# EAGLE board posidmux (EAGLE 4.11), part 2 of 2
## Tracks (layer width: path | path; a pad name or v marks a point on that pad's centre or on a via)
+3V3  (via drill 0.61)
  Top 0.381: D5.C D4.C D6.C D3.C D1.C D8.C D2.C D7.C D12.C D13.C D11.C D14.C D10.C D15.C D9.C D16.C 68.58,106.68 v69.85,107.95
  Bottom 0.381: v69.85,107.95 69.85,108.58 86.36,125.09 XESS.54
AC00  (via drill 0.61)
  Top 0.381: v32.38,87.63 29.21,87.63 27.94,88.9 E27.2 | v31.75,99.06 31.11,98.42 v10.16,98.42 | R37.1 SV3.D
  Bottom 0.381: v32.38,87.63 32.38,98.42 v31.75,99.06 | v10.16,98.42 5.71,93.98 5.71,38.1 16.51,27.3 16.51,12.7 19.05,10.16 63.5,10.16 R37.1 | SV2.6 55.88,43.81 58.42,41.27 58.42,33.66 57.78,33.02 56.52,33.02 55.88,32.38 55.88,24.77 57.15,23.5 57.15,19.68 57.78,19.05 62.87,19.05 62.87,20.32 SV3.D
AC01  (via drill 0.61)
  Top 0.381: v20.32,88.9 19.05,90.17 v1.27,90.17 | v1.27,34.92 17.14,19.05 v52.07,19.05 56.52,19.05 57.78,20.32 SV3.J R39.1
  Bottom 0.381: v20.32,88.9 20.32,86.36 E27.4 | v1.27,34.92 v1.27,90.17 | v52.07,19.05 52.07,23.5 53.34,24.77 SV2.8
AC02  (via drill 0.61)
  Top 0.381: v26.67,76.83 26.04,76.83 24.13,78.74 E27.6 | v32.38,57.15 36.83,57.15 45.72,48.26 46.35,48.26 | 46.35,48.26 46.99,47.62 46.99,45.09 48.26,45.09 SV2.12 | v64.77,45.09 61.59,48.26 46.35,48.26
  Bottom 0.381: SV3.N R41.1 53.98,12.7 55.24,11.43 62.23,11.43 62.23,17.14 64.77,19.68 v64.77,45.09 | v26.67,76.83 28.57,74.93 28.57,73.03 29.21,72.39 32.38,72.39 v32.38,57.15
AC03  (via drill 0.61)
  Top 0.381: v32.38,74.93 29.21,74.93 27.94,73.66 E27.8 | v33.66,55.88 41.91,47.62 41.91,45.09 43.18,45.09 SV2.16 | v43.18,30.48 46.99,30.48 46.99,22.23 48.26,20.95 SV3.T
  Bottom 0.381: R43.1 SV3.T | v32.38,74.93 33.66,73.66 v33.66,55.88 | v43.18,30.48 SV2.16
AC04  (via drill 0.61)
  Top 0.381: v34.29,45.72 36.2,45.72 37.47,44.45 SV2.20 | v33.02,30.48 41.91,30.48 41.91,22.23 43.18,20.95 SV3.X
  Bottom 0.381: R45.1 SV3.X | E27.11 31.11,67.94 31.11,50.8 34.29,47.62 v34.29,45.72 34.29,43.81 33.02,42.55 v33.02,30.48
AC05  (via drill 0.61)
  Top 0.381: v27.94,71.75 28.57,71.75 E27.13 | v27.94,50.8 27.94,48.26 28.57,48.26 29.21,47.62 29.21,45.72 31.11,45.72 32.38,44.45 SV2.24 33.02,43.81 v38.1,38.73
  Bottom 0.381: R47.1 SV3.BB 38.1,20.95 36.83,22.23 36.83,29.84 38.1,31.11 v38.1,38.73 | v27.94,50.8 v27.94,71.75
AC06  (via drill 0.61)
  Top 0.381: v20.95,50.8 24.13,47.62 24.13,45.72 26.04,45.72 27.3,44.45 SV2.28
  Bottom 0.381: R49.1 SV3.FF 33.02,20.95 31.75,22.23 31.75,29.84 30.48,31.11 30.48,41.27 27.94,43.81 SV2.28 | v20.95,50.8 20.95,80.01 24.13,80.01 24.77,80.64 24.77,82.55 31.75,82.55 32.38,81.92 32.38,80.64 E27.15
AC07
  Top 0.381: 4.45,51.44 4.45,49.53 13.34,49.53 19.68,43.18 23.5,43.18 24.77,44.45 SV2.30 | 4.45,51.44 4.45,80.01 6.99,82.55 11.43,82.55 12.7,81.28 14.61,81.28 15.88,80.01 25.4,80.01 29.21,83.82 E27.17 | 4.45,51.44 1.27,51.44 1.27,49.53 21.59,29.21 29.21,29.21 29.21,22.23 27.94,20.95 SV3.LL
  Bottom 0.381: R51.1 SV3.LL
AC08  (via drill 0.61)
  Top 0.381: v20.95,82.55 25.4,82.55 27.94,85.09 31.75,85.09 E25.2
  Bottom 0.381: SV3.RR R53.1 22.23,12.7 20.95,11.43 19.05,11.43 19.05,40.01 22.86,43.81 SV2.32 22.86,45.09 21.59,46.35 21.59,47.62 19.68,49.53 19.68,81.28 v20.95,82.55
AC09  (via drill 0.61)
  Top 0.381: v57.78,80.01 40.64,80.01 36.83,83.82 E25.4 | R38.1 SV3.F
  Bottom 0.381: v57.78,80.01 58.42,79.38 58.42,51.44 63.5,46.35 63.5,26.04 | 63.5,26.04 63.5,24.77 62.23,23.5 62.23,22.23 60.96,20.95 SV3.F | 63.5,26.04 57.78,31.75 SV1.6
AC10  (via drill 0.61)
  Top 0.381: v49.53,59.69 v38.73,59.69
  Bottom 0.381: R40.1 SV3.L 55.88,20.95 54.61,22.23 SV1.8 54.61,32.38 55.88,33.66 55.88,34.92 54.61,36.2 54.61,47.62 52.7,49.53 52.7,56.52 v49.53,59.69 | v38.73,59.69 38.73,76.83 36.83,78.74 E25.6
AC11  (via drill 0.61)
  Top 0.381: v40.01,55.88 46.35,49.53 v50.16,49.53 | v40.01,69.22 E25.8
  Bottom 0.381: R42.1 SV3.R 50.8,20.95 49.53,22.23 SV1.12 49.53,32.38 50.8,33.66 50.8,34.92 52.07,36.2 52.07,47.62 v50.16,49.53 | v40.01,55.88 v40.01,69.22
BAC  (via drill 0.61)
  Top 0.381: E12.11 147.96,67.94 147.96,64.77 158.75,64.77 161.29,67.31 163.83,67.31 166.37,69.85 190.5,69.85 191.77,68.58 E1.11 | v146.05,144.78 90.17,144.78 90.17,142.88 85.72,138.43 6.99,138.43 6.99,125.09 E29.6
  Bottom 0.381: v146.05,144.78 146.05,106.05 140.97,100.97 140.97,92.71 142.24,91.44 142.24,73.66 E12.11
BAC00  (via drill 0.61)
  Top 0.381: v159.38,86.36 E11.3
  Bottom 0.381: SV9.D 182.88,15.88 180.34,13.34 R1.1 179.71,12.7 178.44,11.43 171.45,11.43 171.45,17.14 173.99,19.68 173.99,29.84 172.72,31.11 172.72,43.18 | v159.38,86.36 159.38,61.59 161.29,59.69 167.64,59.69 167.64,51.44 171.45,47.62 171.45,43.81 172.09,43.18 172.72,43.18 | 172.72,43.18 174.62,43.18 174.62,44.45 SV8.6
BAC01  (via drill 0.61)
  Top 0.381: v181.61,21.59 179.71,21.59 178.44,20.32 SV9.J | v180.34,36.2 172.72,43.81 SV8.8
  Bottom 0.381: R3.1 175.26,13.34 177.8,15.88 SV9.J | E11.5 168.28,78.11 168.28,60.33 168.91,59.69 173.99,59.69 173.99,46.35 172.72,45.09 SV8.8 | v181.61,21.59 181.61,29.84 180.34,31.11 v180.34,36.2
BAC02  (via drill 0.61)
  Top 0.381: v153.67,43.18 165.74,43.18 167,44.45 SV8.12 | v156.21,21.59 170.81,21.59 172.09,20.32 SV9.N
  Bottom 0.381: R5.1 170.18,17.14 172.72,19.68 SV9.N | E9.3 153.03,59.05 153.03,48.26 153.67,47.62 v153.67,43.18 154.94,41.91 154.94,31.11 156.21,29.84 v156.21,21.59
BAC03
  Bottom 0.381: R7.1 165.1,13.34 167.64,15.88 SV9.T 167.64,20.95 166.37,22.23 166.37,29.84 165.1,31.11 165.1,41.27 162.56,43.81 SV8.16 162.56,45.09 163.83,46.35 163.83,57.15 E9.5
BAC04  (via drill 0.61)
  Top 0.381: v151.76,52.07 156.21,47.62 156.21,45.09 157.48,45.09 SV8.20
  Bottom 0.381: R9.1 160.02,13.34 162.56,15.88 SV9.X 162.56,20.95 161.29,22.23 161.29,29.84 160.02,31.11 160.02,41.27 157.48,43.81 SV8.20 | v151.76,52.07 151.76,70.48 E10.3
BAC05  (via drill 0.61)
  Top 0.381: v150.5,67.31 157.48,67.31 161.29,71.12 E10.5
  Bottom 0.381: SV9.BB 157.48,15.88 154.94,13.34 R11.1 154.31,12.7 153.03,11.43 148.59,11.43 148.59,17.14 151.13,19.68 151.13,23.5 149.86,24.77 149.86,41.27 152.4,43.81 SV8.24 152.4,45.09 151.13,46.35 151.13,47.62 150.5,48.26 v150.5,67.31
BAC06  (via drill 0.61)
  Top 0.381: E7.5 173.99,71.12 171.45,73.66 E7.3 168.91,73.66 167.64,72.39 v151.76,72.39 | v147.32,29.84 153.67,23.5 153.67,20.95 152.4,20.95 SV9.FF
  Bottom 0.381: R13.1 149.86,13.34 152.4,15.88 SV9.FF | v147.32,29.84 SV8.28 147.32,45.09 148.59,46.35 148.59,47.62 149.22,48.26 149.22,69.85 v151.76,72.39
BAC07
  Bottom 0.381: R15.1 144.78,13.34 146.05,14.61 146.05,18.41 147.32,19.68 SV9.LL 147.32,21.59 144.15,21.59 143.51,22.23 143.51,23.5 144.78,24.77 SV8.30
BAC08  (via drill 0.61)
  Top 0.381: v147.96,59.69 167.64,59.69 168.91,60.96 E6.3
  Bottom 0.381: R17.1 139.7,13.34 142.24,15.88 SV9.RR 142.24,20.95 140.97,22.23 140.97,29.84 142.24,31.11 SV8.32 142.24,45.09 143.51,46.35 143.51,55.24 v147.96,59.69
BAC09  (via drill 0.61)
  Top 0.381: v180.97,55.88 180.34,55.88 E6.5
  Bottom 0.381: R2.1 177.8,13.34 180.34,15.88 SV9.F 180.34,20.95 179.07,22.23 179.07,28.57 176.53,31.11 SV7.6 176.53,32.38 177.8,33.66 177.8,34.92 179.07,36.2 179.07,47.62 180.97,49.53 v180.97,55.88
BAC10  (via drill 0.61)
  Top 0.381: v179.71,85.09 172.72,85.09 171.45,86.36 E8.3
  Bottom 0.381: R4.1 172.72,13.34 175.26,15.88 SV9.L 175.26,20.95 176.53,22.23 176.53,28.57 173.99,31.11 SV7.8 173.99,32.38 175.26,33.66 175.26,34.92 176.53,36.2 176.53,52.07 179.71,55.24 179.71,62.87 182.25,65.41 182.25,82.55 v179.71,85.09
BAC11  (via drill 0.61)
  Top 0.381: v174.62,60.96 172.72,59.05 v172.72,58.42 | v172.72,52.07 v168.91,48.26 | v173.99,83.82 E8.5
  Bottom 0.381: R6.1 167.64,13.34 168.91,14.61 168.91,18.41 170.18,19.68 SV9.R 170.18,20.95 168.91,22.23 SV7.12 168.91,32.38 167.64,33.66 167.64,34.92 168.91,36.2 v168.91,48.26 | v173.99,83.82 173.99,61.59 v174.62,60.96 | v172.72,58.42 v172.72,52.07
BACL
  Top 0.381: E28.7 21.59,119.38 20.32,118.11 16.51,118.11 E29.5
BACLR
  Bottom 0.381: R48.1 SV3.DD 35.56,20.95 34.29,22.23 SV1.24 34.29,32.38 35.56,33.66 35.56,34.92 36.83,36.2 36.83,47.62 43.18,53.98 43.18,67.31 41.91,67.31 41.27,67.94 41.27,71.75 E25.13
BINIT  (via drill 0.61)
  Top 0.381: v179.07,97.16 175.9,93.98 v136.53,93.98 | SV7.32 143.51,31.11 135.89,23.5 135.89,21.59 137.79,21.59 139.06,20.32 SV9.TT
  Bottom 0.381: 138.43,14.61 139.7,15.88 SV9.TT | 138.43,14.61 137.16,13.34 R18.1 | v179.07,97.16 179.07,127 182.88,130.81 E4.5 | v136.53,93.98 136.53,25.4 138.43,23.5 138.43,14.61
BIOP1  (via drill 0.61)
  Top 0.381: v195.58,99.06 184.78,109.86 182.25,109.86 E3.3
  Bottom 0.381: 163.83,14.61 165.1,15.88 SV9.V | 163.83,14.61 162.56,13.34 R8.1 | v195.58,99.06 195.58,20.95 185.42,10.79 185.42,5.71 180.97,1.27 163.83,1.27 163.83,14.61 | 163.83,14.61 SV7.16
BIOP2  (via drill 0.61)
  Top 0.381: v190.5,123.19 186.69,123.19 E3.5 | v200.66,33.66 186.06,19.05 161.93,19.05 160.66,20.32 SV9.Z
  Bottom 0.381: 158.75,14.61 160.02,15.88 SV9.Z | 158.75,14.61 157.48,13.34 R10.1 | v190.5,123.19 193.04,123.19 193.04,114.3 200.66,106.68 v200.66,33.66 | 158.75,14.61 SV7.20
BIOP4  (via drill 0.61)
  Top 0.381: v190.5,93.98 185.42,93.98 E2.3 | v189.23,37.47 182.25,30.48 155.57,30.48 154.31,31.75 SV7.24
  Bottom 0.381: R12.1 152.4,13.34 154.94,15.88 SV9.DD 154.94,20.95 153.67,22.23 SV7.24 | v190.5,93.98 190.5,55.24 189.23,53.98 v189.23,37.47
BIRQ
  Bottom 0.381: R46.1 SV3.Z 40.64,20.95 39.37,22.23 SV1.20 39.37,32.38 40.64,33.66 40.64,34.92 41.91,36.2 41.91,41.27 39.37,43.81 39.37,47.62 45.09,53.34 45.09,76.83 E25.15
BMB
  Bottom 0.381: 68.58,10.79 68.58,67.31 69.85,68.58 E23.11 | 68.58,10.79 70.48,8.89 132.08,8.89 E13.11 | 68.58,10.79 68.58,1.27 19.68,1.27 3.81,17.14 3.81,125.73 E29.2
BMB00  (via drill 0.61)
  Top 0.381: SV6.D R19.1 | v61.59,57.15 76.83,41.91 111.12,41.91 112.39,43.18 | 112.39,43.18 113.67,44.45 SV5.6 | v125.09,39.37 121.28,43.18 112.39,43.18
  Bottom 0.381: v61.59,57.15 61.59,72.39 64.77,72.39 67.94,75.56 67.94,80.01 72.39,80.01 73.03,80.64 73.03,81.92 77.47,86.36 E22.3 | v125.09,39.37 123.19,37.47 123.19,22.23 121.92,20.95 SV6.D
BMB01  (via drill 0.61)
  Top 0.381: v104.78,85.09 88.9,85.09 87.63,83.82 E22.5 | v111.76,30.48 118.11,30.48 118.11,22.23 116.84,20.95 SV6.J
  Bottom 0.381: R21.1 SV6.J | v104.78,85.09 106.05,86.36 106.05,88.27 107.95,90.17 113.03,90.17 113.03,46.35 111.76,45.09 SV5.8 v111.76,30.48
BMB02  (via drill 0.61)
  Top 0.381: v74.3,46.99 78.11,43.18 104.78,43.18 106.05,44.45 SV5.12 | v74.3,73.66 E21.3
  Bottom 0.381: R23.1 SV6.N 111.12,20.32 109.86,21.59 107.95,21.59 107.95,29.84 106.68,31.11 SV5.12 | v74.3,46.99 v74.3,73.66
BMB03  (via drill 0.61)
  Top 0.381: v99.06,40.64 v96.52,40.64
  Bottom 0.381: SV6.X R27.1 100.97,12.7 99.69,11.43 95.25,11.43 95.25,29.84 96.52,31.11 96.52,37.47 99.06,40.01 v99.06,40.64 | 88.27,73.03 89.53,74.3 89.53,87 E19.1 | 88.27,73.03 E21.5 | 88.27,73.03 88.27,61.59 92.71,57.15 92.71,43.18 94.61,43.18 95.89,44.45 SV5.20 v96.52,40.64
BMB03L  (via drill 0.61)
  Top 0.381: v118.75,53.34 113.67,48.26 100.97,48.26 100.33,47.62 100.33,45.09 101.6,45.09 SV5.16
  Bottom 0.381: R25.1 SV6.T 106.68,20.95 105.41,22.23 105.41,27.3 101.6,31.11 SV5.16 | v118.75,53.34 118.75,92.71 100.33,92.71 E19.3
BMB04  (via drill 0.61)
  Top 0.381: v97.16,64.77 92.71,64.77 87.63,59.69 81.28,59.69 80.01,60.96 E20.3 | v95.25,45.72 88.27,45.72 87,44.45 SV5.28 | v83.82,30.48 90.17,30.48 90.17,22.23 91.44,20.95 SV6.FF
  Bottom 0.381: R31.1 SV6.FF | E19.6 97.79,82.55 97.79,65.41 v97.16,64.77 97.16,55.88 95.25,53.98 v95.25,45.72 | v83.82,30.48 83.82,40.01 86.36,42.55 SV5.28
BMB04L  (via drill 0.61)
  Top 0.381: v99.06,73.66 95.25,69.85 90.17,69.85 87.63,67.31 85.09,67.31 v82.55,64.77 | v76.83,30.48 59.69,30.48 59.69,22.23 60.33,21.59 64.77,21.59 64.77,19.68 65.41,19.05 94.61,19.05 95.89,20.32 SV6.BB
  Bottom 0.381: SV6.BB R29.1 | v99.06,73.66 99.06,82.55 100.33,83.82 E19.5 | 82.55,50.16 82.55,46.35 83.19,45.72 87.63,45.72 87.63,43.81 88.27,43.18 90.81,43.18 90.81,44.45 SV5.24 | 82.55,50.16 v82.55,64.77 | v76.83,30.48 77.47,31.11 77.47,41.27 80.01,43.81 80.01,47.62 82.55,50.16
BMB05  (via drill 0.61)
  Top 0.381: SV5.32 80.64,44.45 79.38,45.72 78.11,45.72 75.56,48.26 71.75,48.26 71.75,57.78 73.66,59.69 80.01,59.69 81.28,58.42 E20.5 88.27,58.42 v90.81,60.96
  Bottom 0.381: R35.1 SV6.RR 81.28,20.95 80.01,22.23 80.01,29.84 78.74,31.11 78.74,41.27 81.28,43.81 SV5.32 | v90.81,60.96 90.81,75.56 E18.1
BMB05L  (via drill 0.61)
  Top 0.381: v83.82,69.85 88.9,69.85 92.71,73.66 E18.3 | v85.09,48.26 85.09,45.09 83.82,45.09 SV5.30 | v82.55,21.59 84.45,21.59 85.72,20.32 SV6.LL
  Bottom 0.381: R33.1 SV6.LL | v83.82,69.85 83.82,49.53 v85.09,48.26 | v82.55,21.59 82.55,29.84 81.28,31.11 81.28,41.27 83.82,43.81 SV5.30
BMB06  (via drill 0.61)
  Top 0.381: v111.12,72.39 104.14,72.39 102.87,73.66 E18.6 | v115.57,45.72 v110.49,45.72
  Bottom 0.381: v111.12,72.39 111.76,73.03 111.76,83.82 E16.3 | R22.1 SV6.L 114.3,20.95 113.03,22.23 SV4.8 113.03,32.38 114.3,33.66 114.3,34.92 115.57,36.2 v115.57,45.72 | v110.49,45.72 110.49,47.62 111.76,48.9 111.76,62.23 107.95,62.23 101.6,55.88 101.6,54.61 99.69,54.61 98.42,55.88 98.42,61.59 99.06,62.23 99.06,71.12 E18.6
BMB06L  (via drill 0.61)
  Top 0.381: v114.3,53.98 107.31,53.98 107.31,65.41 E18.5
  Bottom 0.381: R20.1 SV6.F 119.38,20.95 120.65,22.23 120.65,26.04 115.57,31.11 SV4.6 115.57,32.38 116.84,33.66 116.84,34.92 118.11,36.2 118.11,50.16 v114.3,53.98
BMB07  (via drill 0.61)
  Top 0.381: 104.14,66.04 106.05,64.14 v106.05,53.98 | 104.14,66.04 102.87,67.31 100.33,67.31 99.06,66.04 E17.1 | v106.05,83.82 107.31,85.09 114.3,85.09 115.57,83.82 E16.5 | 104.14,66.04 v104.78,66.04 | SV6.V 104.14,20.95 102.87,22.23 SV4.16
  Bottom 0.381: R26.1 SV6.V | v106.05,53.98 103.5,51.44 103.5,49.53 105.41,47.62 105.41,36.2 104.14,34.92 104.14,33.66 102.87,32.38 SV4.16 | v106.05,83.82 104.78,82.55 v104.78,66.04
BMB07L  (via drill 0.61)
  Top 0.381: v104.78,50.8 104.78,60.33 102.87,62.23 96.52,62.23 95.25,60.96 E17.3
  Bottom 0.381: SV6.R R24.1 109.86,12.7 111.12,11.43 113.03,11.43 113.03,20.95 112.39,21.59 111.12,21.59 110.49,22.23 110.49,28.57 107.95,31.11 SV4.12 107.95,32.38 109.22,33.66 109.22,34.92 107.95,36.2 107.95,47.62 v104.78,50.8
BMB08  (via drill 0.61)
  Top 0.381: v73.03,57.15 96.52,57.15 100.33,60.96 E17.6
  Bottom 0.381: E17.6 107.31,66.67 107.31,71.75 E15.3 | SV4.24 92.71,22.23 93.98,20.95 SV6.DD R30.1 93.34,12.7 93.34,11.43 78.11,11.43 73.03,16.51 v73.03,57.15
BMB08L  (via drill 0.61)
  Top 0.381: v102.23,50.8 102.23,57.78 E17.5
  Bottom 0.381: R28.1 SV6.Z 99.06,20.95 97.79,22.23 SV4.20 97.79,32.38 99.06,33.66 99.06,34.92 100.33,36.2 100.33,45.72 102.23,45.72 102.87,46.35 102.87,47.62 102.23,48.26 v102.23,50.8
BMB09  (via drill 0.61)
  Top 0.381: v121.92,33.02 89.53,33.02 88.27,31.75 SV4.28 | v121.92,66.04 E15.5 | v87.63,29.21 87.63,22.23 88.9,20.95 SV6.JJ
  Bottom 0.381: R32.1 SV6.JJ | v121.92,33.02 v121.92,66.04 | v87.63,29.21 SV4.28
BMB10
  Bottom 0.381: R34.1 SV6.NN 83.82,20.95 85.09,22.23 SV4.30 85.09,32.38 86.36,33.66 86.36,35.56 93.34,35.56 97.79,40.01 97.79,49.53 E14.3
BMB11  (via drill 0.61)
  Top 0.381: v119.38,35.56 79.38,35.56 78.74,34.92 78.74,33.02 80.64,33.02 81.92,31.75 | 81.92,31.75 79.38,29.21 74.93,29.21 74.93,22.23 75.56,21.59 76.83,21.59 78.11,20.32 SV6.TT | 81.92,31.75 SV4.32
  Bottom 0.381: R36.1 SV6.TT | v119.38,35.56 120.65,36.83 120.65,48.9 117.47,52.07 117.47,57.78 E14.5
BMBL
  Bottom 0.381: E29.1 16.51,128.27 20.32,128.27 20.32,127 E28.5
BRUN  (via drill 0.61)
  Top 0.381: v66.04,121.28 177.16,121.28 E4.3 | v67.31,14.61 64.14,11.43 32.38,11.43 31.11,12.7 R50.1
  Bottom 0.381: R50.1 SV3.JJ 30.48,20.95 29.21,22.23 SV1.28 | v66.04,121.28 59.69,114.94 59.69,52.07 67.31,44.45 v67.31,14.61
BSKIP  (via drill 0.61)
  Top 0.381: v46.35,67.31 45.72,67.31 44.45,68.58 E25.11
  Bottom 0.381: R44.1 SV3.V 45.72,20.95 44.45,22.23 SV1.16 44.45,32.38 45.72,33.66 45.72,34.92 49.53,38.73 49.53,47.62 48.26,48.9 48.26,65.41 v46.35,67.31
BTS1  (via drill 0.61)
  Top 0.381: v184.78,31.11 182.88,29.21 151.76,29.21 149.86,31.11 149.86,33.02 147.96,33.02 146.69,31.75 SV7.30 146.05,22.23 144.78,20.95 SV9.NN
  Bottom 0.381: R16.1 142.24,13.34 144.78,15.88 SV9.NN | v184.78,31.11 184.78,52.07 187.96,55.24 187.96,93.98 184.15,97.79 184.15,139.06 182.25,139.06 E5.3
BTS3  (via drill 0.61)
  Top 0.381: v186.06,30.48 183.51,27.94 151.76,27.94 148.59,31.11 SV7.28
  Bottom 0.381: R14.1 147.32,17.14 149.86,19.68 SV9.JJ 149.86,20.95 148.59,22.23 SV7.28 | v186.06,30.48 186.06,52.07 189.23,55.24 189.23,137.16 182.88,143.51 E5.5
CAF_L
  Top 0.381: E4.6 177.8,134.62 149.22,134.62 140.34,143.51 XESS.33
CLRAC  (via drill 0.61)
  Top 0.381: v50.8,86.36 RN2.12 | v133.35,109.22 131.44,107.31 71.12,107.31 69.22,105.41 56.52,105.41 55.24,104.14 v52.7,104.14
  Bottom 0.381: v50.8,86.36 50.16,87 50.16,92.71 46.35,96.52 D14.A 45.72,97.16 v52.7,104.14 | v133.35,109.22 133.35,139.06 137.16,142.88 XESS.34
GND  (via drill 0.61)
  Top 0.381: 52.7,90.17 50.16,87.63 46.99,87.63 E25.17 | 52.7,90.17 60.96,90.17 62.23,91.44 E23.1 64.77,91.44 66.04,90.17 76.2,90.17 77.47,88.9 E22.2 E22.7 | 52.7,90.17 46.99,90.17 45.72,88.9 E25.19 | E21.2 E21.7 | E22.4 E23.17 | E20.7 E20.2 67.94,63.5 65.41,66.04 C23.2 | 114.3,63.5 E14.7 | 114.3,63.5 E14.2 | E14.4 114.3,63.5 | SV5.10 SV5.9 | SV5.9 SV5.7 SV5.5 SV5.3 SV5.1 | SV5.18 SV5.17 SV5.19 SV5.21 SV5.23 SV5.25 SV5.27 | SV5.13 SV5.14 | SV5.13 SV5.11 SV5.9 | SV5.13 SV5.15 | SV5.33 SV5.31 SV5.29 | SV2.33 SV2.34 | SV2.31 SV2.33 | SV2.27 SV2.29 | C38.- 11.43,52.7 17.14,46.99 SV2.33 | SV2.9 SV2.10 | SV2.9 SV2.7 SV2.5 SV2.3 SV2.1 | SV2.18 SV2.17 SV2.19 SV2.21 SV2.23 SV2.25 | SV2.14 SV2.13 SV2.15 | SV2.11 SV2.9 | SV3.HH SV3.EE SV3.CC SV3.AA SV3.Y | SV3.U SV3.W | SV3.S SV3.P SV3.M SV3.K SV3.H | SV3.E SV3.C SV3.A SV3.B SV6.VV | SV1.10 SV1.9 | SV1.9 SV1.7 SV1.5 SV1.3 SV1.1 | SV3.VV SV3.UU SV3.SS SV3.PP SV3.MM | SV1.17 SV1.18 | SV1.17 SV1.15 SV1.13 | SV1.13 SV1.14 | SV1.13 SV1.11 SV1.9 | SV1.34 SV1.33 SV1.31 SV1.29 SV1.27 SV1.25 | SV1.25 SV1.26 | SV1.25 SV1.23 SV1.21 | SV1.21 SV1.22 | SV1.21 SV1.19 SV1.17 | SV4.1 SV4.3 SV4.5 SV4.7 SV4.9 SV4.11 SV4.13 SV4.15 SV4.17 SV4.19 SV4.21 SV4.23 SV4.25 SV4.27 SV4.29 SV4.31 SV4.33 | SV6.A SV6.B | SV6.UU SV6.SS SV6.PP SV6.MM SV6.KK | SV6.EE SV6.CC SV6.AA SV6.Y SV6.W | SV6.U SV6.S SV6.P SV6.M SV6.K SV6.H | SV6.E SV6.C SV6.A | C26.2 37.47,116.84 38.73,118.11 45.72,118.11 46.99,116.84 E24.8 | C43.1 42.55,109.22 41.27,110.49 28.57,110.49 24.77,114.3 C28.2 14.61,114.3 12.06,116.84 C29.2 | E26.7 34.29,119.38 33.02,118.11 25.4,118.11 24.13,116.84 E28.8 | v27.3,132.08 E28.15 31.75,132.08 33.02,133.35 53.34,133.35 54.61,132.08 E24.15 80.64,132.08 91.44,142.88 XESS.52 92.08,143.51 104.78,130.81 173.99,130.81 174.62,130.18 175.9,130.18 E4.7
  Top 0.381: SV9.B SV9.A SV9.C SV9.E SV9.H SV9.K SV9.M SV9.P SV9.S SV9.U SV9.W SV9.Y SV9.AA SV9.CC | SV9.UU SV9.SS SV9.PP SV9.MM | SV9.KK SV9.HH SV9.EE | SV7.9 SV7.10 | SV7.9 SV7.7 SV7.5 SV7.3 SV7.1 | SV7.17 SV7.18 | SV7.17 SV7.15 SV7.13 | SV7.13 SV7.14 | SV7.13 SV7.11 SV7.9 | SV7.34 SV7.33 SV7.31 SV7.29 SV7.27 SV7.25 | SV7.25 SV7.26 | SV7.25 SV7.23 SV7.21 | SV7.21 SV7.22 | SV7.21 SV7.19 SV7.17 | SV8.17 SV8.18 | SV8.17 SV8.15 SV8.13 | SV8.13 SV8.14 | SV8.13 SV8.11 SV8.9 | SV8.34 SV8.33 SV8.31 SV8.29 SV8.27 SV8.25 | SV8.25 SV8.26 | SV8.25 SV8.23 SV8.21 SV8.22 | SV8.19 SV8.17 | SV8.9 SV8.10 | SV8.9 SV8.7 SV8.5 SV8.3 SV8.1 184.78,46.99 190.5,52.7 C39.- | 175.26,63.5 E6.7 | 175.26,63.5 E6.2 E9.7 E9.2 144.15,63.5 141.6,66.04 C12.2 | 175.26,63.5 E6.4 | E13.10 125.73,68.58 127,69.85 137.16,69.85 138.43,68.58 E12.10 | E5.4 184.15,138.43 C5.2 | E3.4 184.15,113.03 C3.2 187.96,113.03 191.13,116.2 X1.5 | C4.2 184.15,125.73 E4.4 E3.7 | E3.2 E2.7 178.44,106.05 179.71,106.05 E2.6 | E2.4 184.15,100.33 C2.2 | E1.18 191.77,86.36 186.69,91.44 E1.1 184.15,91.44 181.61,88.9 E8.7 E8.2 E11.7 E11.2 153.67,88.9 151.13,86.36 E12.18 146.69,85.72 146.69,85.09 | E15.2 E15.7 | E16.2 E16.7 121.92,88.9 123.19,90.17 | 123.19,90.17 E13.1 | 137.16,90.17 138.43,91.44 E12.1 | 137.16,90.17 123.19,90.17 | E7.7 E7.2 E10.7 E10.2 | E13.18 131.44,85.72 131.44,84.45 E13.17 133.35,83.82 134.62,85.09 143.51,85.09 | 146.69,85.09 146.69,84.45 E12.17 E11.4 | 146.69,85.09 143.51,85.09 | 137.16,90.17 137.16,88.9 138.43,87.63 140.97,87.63 143.51,85.09 | SV6.A 127,20.32 SV9.VV | J2.3 35.56,144.15 38.1,144.15 J2.2
  Bottom 0.381: E23.17 70.48,84.45 70.48,85.72 E23.18 | E22.2 80.01,88.9 81.92,87 81.92,85.72 80.01,83.82 E22.4 80.01,82.55 C22.2 80.64,81.28 80.64,78.11 E21.2 80.64,74.3 80.64,68.58 | C23.2 64.77,66.67 64.14,67.31 64.14,67.94 E23.10 | 80.64,65.41 80.64,68.58 | 80.64,65.41 E20.2 | E21.4 80.01,69.85 C21.2 80.64,68.58 | 80.64,65.41 80.64,60.33 E20.4 79.38,57.78 79.38,57.15 80.01,56.52 C20.2 80.01,55.24 78.74,53.98 SV5.33 SV5.34 | E14.4 110.49,57.15 C14.2 110.49,55.24 109.22,53.98 SV5.9 | E14.2 111.12,65.41 111.12,68.58 C15.2 110.49,69.85 E15.4 | E19.4 94.61,83.19 94.61,82.55 95.25,81.92 C19.2 95.89,81.28 95.89,73.03 E18.4 95.25,69.85 C18.2 95.25,67.94 95.89,67.31 95.89,55.88 C17.2 | SV5.15 SV5.17 | SV5.27 SV5.29 | SV5.25 SV5.26 | C17.2 95.25,56.52 94.61,57.15 94.61,57.78 E17.4 | SV5.22 SV5.21 93.98,53.98 95.25,55.24 C17.2 | E27.10 24.13,67.31 C27.2 24.13,65.41 22.86,64.14 SV2.31 SV2.29 | SV2.15 SV2.17 | SV2.13 SV2.11 | SV2.26 SV2.25 SV2.27 | E25.10 36.83,67.31 C25.2 36.83,65.41 35.56,64.14 SV2.21 SV2.22 | SV3.W SV3.Y | SV3.S SV3.U | SV3.E SV3.H | SV3.MM SV3.KK | SV3.PP 22.86,23.5 21.59,24.77 SV1.34 | SV3.P 50.8,23.5 52.07,24.77 SV1.10 | SV4.10 SV4.9 110.49,42.55 109.22,43.81 SV5.10 | SV4.17 SV4.18 100.33,31.11 99.06,29.84 SV6.Y | SV4.13 SV4.14 | SV4.33 SV4.34 | SV4.25 SV4.26 | SV4.21 SV4.22 | SV6.UU SV6.VV | SV6.KK SV6.HH SV6.EE | SV6.U SV6.W | SV6.E SV6.H | SV2.14 45.72,43.81 44.45,42.55 SV1.15 | C26.2 36.83,117.47 36.2,118.11 36.2,118.75 E26.7 | E24.8 49.53,115.57 C24.2 | C29.2 11.43,117.47 10.79,118.11 10.79,118.75 E29.7 | C28.2 24.13,115.57 E28.8 27.3,121.28 v27.3,132.08 | E28.15 34.29,135.89 J2.3 | SV9.UU SV9.VV | SV9.KK SV9.MM
  Bottom 0.381: SV9.EE 152.4,23.5 151.13,24.77 SV7.26 | SV9.M 172.72,23.5 171.45,24.77 SV7.10 | SV8.21 SV8.19 157.48,47.62 156.21,48.9 C9.2 156.21,57.15 E9.4 156.84,60.33 156.84,65.41 | E1.10 186.69,67.31 C1.2 186.69,65.41 182.25,60.96 182.25,49.53 180.34,47.62 SV8.1 | SV7.9 171.45,34.92 170.18,36.2 SV8.10 | E6.4 171.45,57.15 C6.2 | E6.2 172.09,65.41 172.09,68.58 C7.2 171.45,69.85 E7.4 172.09,73.03 172.09,78.11 | C13.2 125.73,66.67 125.09,67.31 125.09,67.94 E13.10 | C12.2 140.97,66.67 140.34,67.31 140.34,67.94 E12.10 | 156.84,65.41 156.84,68.58 C10.2 156.21,69.85 E10.4 | E9.2 156.84,65.41 | E4.7 E5.2 E5.7 | E4.7 E5.4 | E2.7 E2.2 | E3.2 E3.7 E4.2 E4.7 | E3.4 182.88,110.49 180.34,107.95 E2.6 180.34,105.41 182.88,102.87 E2.4 182.88,97.79 184.78,95.89 184.78,92.08 E1.1 | E1.17 192.41,84.45 192.41,85.72 E1.18 | C16.2 110.49,81.92 109.86,82.55 109.86,83.19 E16.4 107.31,85.72 | 107.31,85.72 107.31,87 E16.2 | 107.31,85.72 107.31,78.11 E15.2 | 172.09,78.11 172.09,81.28 C8.2 171.45,82.55 E8.4 | E7.2 172.09,78.11 | E10.2 156.84,78.11 156.84,81.28 C11.2 156.21,82.55 E11.4
IOP  (via drill 0.61)
  Top 0.381: E26.5 v39.37,124.46
  Bottom 0.381: v39.37,124.46 41.27,126.36 41.27,127.64 E26.12
IOP1  (via drill 0.61)
  Top 0.381: v176.53,147.96 174.62,149.86 v54.61,149.86 | v38.1,132.08 36.83,130.81 v12.06,130.81
  Bottom 0.381: v176.53,147.96 176.53,114.3 175.26,113.03 E3.1 | v54.61,149.86 38.1,133.35 v38.1,132.08 | v12.06,130.81 12.06,128.91 E29.4
IOP1L
  Top 0.381: E28.6 20.32,121.92 19.05,120.65 15.88,120.65 15.88,123.83 E29.3 9.53,130.18 8.26,130.18 8.26,132.72 8.89,133.35 31.75,133.35 33.02,134.62 E26.1
IOP2
  Top 0.381: E29.8 19.05,119.38 20.32,120.65 64.77,120.65 66.04,119.38 172.72,119.38 174.62,117.47 178.44,117.47 E3.6
IOP2L
  Top 0.381: E29.9 19.05,121.92 20.32,123.19 26.67,123.19 27.94,121.92 E28.11
  Bottom 0.381: E26.2 32.38,128.91 32.38,123.83 E28.11
IOP4  (via drill 0.61)
  Top 0.381: v170.18,129.54 v66.04,129.54 | v60.96,139.7 v30.48,139.7
  Bottom 0.381: v170.18,129.54 170.18,105.41 175.26,100.33 E2.1 | v66.04,129.54 60.96,134.62 v60.96,139.7 | v30.48,139.7 27.94,142.24 19.68,142.24 19.68,130.18 21.59,128.27 24.77,128.27 24.77,123.83 24.13,123.19 18.41,123.19 18.41,123.83 E29.10
IOP4L  (via drill 0.61)
  Top 0.381: v39.37,126.36 38.73,125.73 20.32,125.73 19.05,127 E29.11 | v19.05,116.84 20.32,116.84 21.59,118.11 24.13,118.11 25.4,119.38 E28.10
  Bottom 0.381: v39.37,126.36 40.01,127 40.01,128.91 E26.13 | v19.05,116.84 17.78,118.11 15.88,118.11 15.88,125.09 E29.11
IOPL  (via drill 0.61)
  Top 0.381: 33.02,90.17 34.29,91.44 E25.1 | 33.02,90.17 31.75,88.9 E27.19 | 33.02,90.17 25.4,90.17 24.13,91.44 E27.1 | v28.57,123.19 31.75,123.19 33.02,121.92 E26.6
  Bottom 0.381: v28.57,123.19 28.57,116.2 29.21,115.57 32.38,115.57 32.38,100.33 34.92,97.79 34.92,92.08 E25.1
IRQ  (via drill 0.61)
  Top 0.381: v53.34,88.9 RN2.14 | v132.08,104.78 131.44,104.14 v57.15,104.14
  Bottom 0.381: v53.34,88.9 51.44,90.81 51.44,96.52 D15.A 50.8,97.79 v57.15,104.14 | XESS.36 v132.08,104.78
MX_0  (via drill 0.61)
  Top 0.381: v27.3,139.7 28.57,140.97 75.56,140.97 78.11,143.51 XESS.57
  Bottom 0.381: v27.3,139.7 27.3,136.53 E28.2
MX_00XX
  Bottom 0.381: E28.12 28.57,126.36 28.57,140.34 27.94,140.97 23.5,140.97 23.5,135.25 E28.1
MX_1  (via drill 0.61)
  Top 0.381: v20.95,139.7 23.5,142.24 60.33,142.24 62.87,144.78 79.38,144.78 80.64,143.51 XESS.56
  Bottom 0.381: v20.95,139.7 20.95,131.44 E28.3
MX_2
  Bottom 0.381: E28.14 34.29,133.35 36.83,133.35 53.34,149.86 53.34,150.5 53.98,151.13 93.98,151.13 XESS.51
MX_3  (via drill 0.61)
  Top 0.381: v87.63,130.81 46.99,130.81 44.45,128.27 41.91,128.27 41.27,127.64 37.47,127.64 36.83,128.27 33.02,128.27 31.75,127 E28.13
  Bottom 0.381: v87.63,130.81 96.52,139.7 XESS.50
N$1  (via drill 0.61)
  Top 0.381: v61.59,93.98 v76.83,93.98
  Bottom 0.381: v61.59,93.98 61.59,90.81 E23.2 | v76.83,93.98 78.11,92.71 78.11,92.08 E22.1
N$2
  Top 0.381: E23.5 61.59,83.19 61.59,85.09 83.82,85.09 85.09,86.36 E22.6
N$3
  Top 0.381: E23.6 68.58,78.74 69.85,80.01 76.2,80.01 77.47,78.74 E21.1
N$4
  Top 0.381: E23.9 64.77,71.12 66.04,69.85 81.28,69.85 85.09,73.66 E21.6
N$5  (via drill 0.61)
  Top 0.381: E23.12 v75.56,71.12
  Bottom 0.381: v75.56,71.12 78.11,68.58 78.11,66.67 E20.1
N$6  (via drill 0.61)
  Top 0.381: v128.27,64.77 121.92,64.77 118.11,60.96 E14.6
  Bottom 0.381: v128.27,64.77 128.27,76.83 130.18,78.74 E13.15
N$7
  Top 0.381: E14.1 110.49,66.04 114.94,70.48 114.94,72.39 118.11,72.39 120.65,69.85 125.73,69.85 127,71.12 E13.12
N$8
  Top 0.381: E15.6 118.11,73.66 120.65,71.12 E13.9
N$9
  Top 0.381: E15.1 110.49,78.74 111.76,80.01 121.92,80.01 123.19,78.74 E13.6
N$10  (via drill 0.61)
  Top 0.381: v121.92,83.82 120.65,83.82 118.11,86.36 E16.6
  Bottom 0.381: v121.92,83.82 E13.5
N$11  (via drill 0.61)
  Top 0.381: v121.92,90.81 121.28,90.17 111.76,90.17 110.49,91.44 E16.1
  Bottom 0.381: v121.92,90.81 123.19,89.53 123.19,88.9 E13.2
N$12  (via drill 0.61)
  Top 0.381: v73.03,62.23 83.82,62.23 85.09,60.96 E20.6
  Bottom 0.381: v73.03,62.23 73.03,76.83 E23.15
N$13
  Top 0.381: E12.2 140.97,88.9 142.24,90.17 152.4,90.17 153.67,91.44 E11.1
N$14
  Top 0.381: E12.5 140.97,81.28 142.24,82.55 157.48,82.55 161.29,86.36 E11.6
N$15  (via drill 0.61)
  Top 0.381: v26.67,92.71 12.7,92.71 11.43,91.44 RN1.1 | v26.67,87.63 27.94,86.36 E27.18
  Bottom 0.381: v26.67,92.71 v26.67,87.63
N$16  (via drill 0.61)
  Top 0.381: v8.26,72.39 v24.77,72.39
  Bottom 0.381: v8.26,72.39 8.26,84.45 RN1.3 | v24.77,72.39 25.4,73.03 25.4,78.74 27.94,81.28 E27.16
N$17  (via drill 0.61)
  Top 0.381: v13.97,80.01 12.7,80.01 11.43,81.28 RN1.5 | v15.88,69.85 v24.77,69.85 | v26.67,74.93 27.94,76.2 E27.14
  Bottom 0.381: v13.97,80.01 15.88,78.11 v15.88,69.85 | v24.77,69.85 26.67,71.75 v26.67,74.93
N$18  (via drill 0.61)
  Top 0.381: v13.34,69.85 15.88,67.31 25.4,67.31 29.21,71.12 E27.12
  Bottom 0.381: v13.34,69.85 13.34,73.03 RN1.7
N$19
  Top 0.381: RN1.8 7.62,73.66 6.99,73.03 6.99,71.12 E27.9
N$20
  Top 0.381: RN1.6 11.43,78.74 12.7,77.47 20.32,77.47 21.59,76.2 E27.7
N$21
  Top 0.381: E12.6 140.97,78.74 143.51,76.2 144.78,76.2 146.05,74.93 148.59,74.93 149.22,74.3 149.22,66.04 E9.1
N$22  (via drill 0.61)
  Top 0.381: v137.79,66.04 141.6,62.23 160.02,62.23 161.29,60.96 E9.6
  Bottom 0.381: v137.79,66.04 137.79,69.22 E12.9
N$23
  Bottom 0.381: E12.12 E10.1
N$24
  Top 0.381: E8.6 180.34,86.36 184.15,82.55 186.69,82.55 189.87,79.38 189.87,74.93 194.31,74.93 194.94,75.56 194.94,78.11 193.68,78.11 E1.15
N$25  (via drill 0.61)
  Top 0.381: v173.99,90.17 172.72,90.17 171.45,91.44 E8.1 | v175.26,74.93 179.07,74.93 179.71,74.3 179.71,73.03 183.51,73.03 184.15,72.39 190.5,72.39 191.77,71.12 E1.12
  Bottom 0.381: v173.99,90.17 175.26,88.9 v175.26,74.93
N$26  (via drill 0.61)
  Top 0.381: v175.26,72.39 179.07,72.39 180.34,71.12 E1.9
  Bottom 0.381: v175.26,72.39 175.26,63.5 E6.6
N$27  (via drill 0.61)
  Top 0.381: v182.25,63.5 180.97,63.5 179.71,64.77 172.72,64.77 171.45,66.04 E6.1
  Bottom 0.381: v182.25,63.5 183.51,64.77 183.51,76.83 E1.6
N$28  (via drill 0.61)
  Top 0.381: v179.71,80.01 180.97,81.28 E1.5
  Bottom 0.381: v179.71,80.01 179.71,75.56 E7.6
N$29
  Top 0.381: E12.15 148.59,78.74 152.4,74.93 160.02,74.93 161.29,73.66 E10.6
N$30  (via drill 0.61)
  Top 0.381: v168.28,87.63 182.88,87.63 184.15,88.9 E1.2
  Bottom 0.381: v168.28,87.63 168.28,80.64 E7.1
N$31
  Top 0.381: RN1.4 11.43,83.82 12.7,82.55 19.05,82.55 20.32,81.28 E27.5
N$32
  Top 0.381: RN1.2 11.43,88.9 15.24,85.09 19.05,85.09 20.32,86.36 E27.3
N$33
  Top 0.381: E25.16 44.45,81.28 46.99,83.82 RN2.4
N$34
  Top 0.381: E25.18 44.45,86.36 46.99,88.9 RN2.2
N$35
  Top 0.381: E25.14 44.45,76.2 46.99,78.74 RN2.6
N$36
  Top 0.381: E25.12 44.45,71.12 46.99,73.66 RN2.8
N$37
  Bottom 0.381: E25.9 37.47,73.03 37.47,76.83 36.83,77.47 33.66,77.47 33.66,79.38 34.29,80.01 46.35,80.01 46.35,78.11 RN2.7
N$38  (via drill 0.61)
  Top 0.381: v50.16,74.93 38.1,74.93 36.83,76.2 E25.7
  Bottom 0.381: v50.16,74.93 50.16,79.38 RN2.5
N$39
  Bottom 0.381: E25.5 36.83,81.28 40.64,85.09 46.99,85.09 46.99,86.36 RN2.3
N$40
  Top 0.381: E25.3 36.83,86.36 40.64,90.17 45.09,90.17 46.35,91.44 RN2.1
N$41
  Top 1.905: FUSE.1 J2.4
N$42
  Bottom 0.381: RN2.16 D16.A
N$43
  Top 0.381: E24.14 57.15,129.54 58.42,128.27 187.96,128.27 191.13,125.09 X1.2
N$44
  Top 0.381: E24.7 49.53,119.38 50.8,118.11 57.15,118.11 58.42,116.84 173.99,116.84 175.26,115.57 186.06,115.57 191.13,120.65 193.68,120.65 X1.8
N$45
  Top 0.381: E24.13 186.06,127 186.69,126.36 186.69,124.46 185.42,124.46 181.61,120.65 181.61,116.84 186.06,116.84 191.13,121.92 X1.3
N$46
  Bottom 0.381: C42.2 41.27,109.22 45.09,113.03 50.8,113.03 50.8,121.92 E24.5
N$47
  Bottom 0.381: C42.1 40.64,124.46 41.91,125.73 46.99,125.73 46.99,127 E24.4
N$48  (via drill 0.61)
  Top 0.381: v33.66,123.19 44.45,123.19 46.35,125.09 46.35,128.91 47.62,128.91 E24.3
  Bottom 0.381: v33.66,123.19 33.66,111.76 35.56,109.86 C40.2
N$49  (via drill 0.61)
  Top 0.381: v53.98,111.76 38.73,111.76 36.2,114.3 C40.1
  Bottom 0.381: v53.98,111.76 59.69,117.47 59.69,147.96 59.05,148.59 54.61,148.59 54.61,142.24 48.9,136.53 48.9,135.25 E24.1
N$50  (via drill 0.61)
  Top 0.381: v38.1,128.91 40.01,130.81 45.72,130.81 46.99,132.08 E24.2
  Bottom 0.381: C41.1 v38.1,128.91
N$51
  Bottom 0.381: C43.2 43.18,114.94 46.35,118.11 46.35,120.02 E24.6
PD_0  (via drill 0.61)
  Top 0.381: E23.3 64.77,86.36 66.04,87.63 v75.56,87.63 137.16,87.63 138.43,86.36 E12.3 | v27.3,102.87 50.8,102.87 52.7,100.97 78.74,100.97 80.64,99.06 XESS.71
  Bottom 0.381: RN1.16 20.32,93.98 D1.A 20.95,96.52 v27.3,102.87 | v75.56,87.63 75.56,95.25 76.83,95.25 80.64,99.06 XESS.71
PD_1  (via drill 0.61)
  Top 0.381: v24.77,87.63 20.32,87.63 19.05,86.36 RN1.14 | E23.4 64.77,83.82 66.04,82.55 v83.82,82.55 137.16,82.55 138.43,83.82 E12.4 | v29.21,101.6 49.53,101.6 51.44,99.69 60.96,99.69 62.87,97.79 v85.09,97.79
  Bottom 0.381: v24.77,87.63 25.4,88.27 D2.A 25.4,97.16 29.21,100.97 v29.21,101.6 | v83.82,82.55 83.82,91.44 85.09,92.71 v85.09,97.79 85.09,106.05 121.92,142.88 XESS.40
PD_2  (via drill 0.61)
  Top 0.381: E23.7 64.77,76.2 66.04,77.47 v88.27,77.47 137.16,77.47 138.43,76.2 E12.7 | v90.17,102.87 52.07,102.87 50.8,104.14 26.04,104.14 26.04,102.23 27.94,100.33 33.02,100.33 33.02,98.42 29.21,94.61 20.32,94.61 18.41,96.52 D3.A
  Bottom 0.381: RN1.12 15.88,83.19 15.88,93.98 17.78,95.89 D3.A | v88.27,77.47 88.27,87 90.17,88.9 v90.17,102.87 90.17,108.58 124.46,142.88 XESS.39
PD_3  (via drill 0.61)
  Top 0.381: v135.89,111.76 132.08,115.57 v127,115.57 125.73,114.3 v77.47,114.3 | v14.61,76.2 RN1.10 | v57.15,69.85 60.96,73.66 E23.8 | v57.15,62.23 53.34,58.42 v18.41,58.42 | v71.12,95.25 v68.58,95.25
  Bottom 0.381: v135.89,111.76 135.89,98.42 137.79,96.52 137.79,75.56 E12.8 | XESS.38 v127,115.57 | D4.A 12.7,78.11 v14.61,76.2 14.61,62.23 v18.41,58.42 | v57.15,69.85 v57.15,62.23 | v77.47,114.3 72.39,109.22 72.39,96.52 v71.12,95.25 | v68.58,95.25 66.67,93.34 66.67,76.83 E23.8
PD_4  (via drill 0.61)
  Top 0.381: v6.99,74.93 15.24,74.93 16.51,73.66 RN1.9 | 73.66,74.93 72.39,73.66 E23.13 | 73.66,74.93 144.78,74.93 146.05,73.66 E12.13 | v149.86,133.35 145.41,133.35 135.25,143.51 XESS.35 | v18.41,62.23 19.68,60.96 v49.53,60.96 | v52.7,68.58 56.52,72.39 57.15,72.39 59.69,74.93 73.66,74.93
  Bottom 0.381: v6.99,74.93 6.99,92.71 10.16,95.89 D5.A | v149.86,133.35 151.13,132.08 151.13,97.79 150.5,97.16 150.5,75.56 148.59,73.66 E12.13 | v18.41,62.23 18.41,73.03 RN1.9 | v49.53,60.96 52.7,64.14 v52.7,68.58
PD_5  (via drill 0.61)
  Top 0.381: v143.51,101.6 107.31,101.6 104.78,99.06 XESS.80 103.5,99.06 98.42,93.98 v83.82,93.98 | v66.04,63.5 64.77,64.77 36.2,64.77 34.92,63.5 13.34,63.5 5.71,71.12 5.71,80.01 11.43,80.01 12.7,78.74 RN1.11 | E23.14 v75.56,76.2
  Bottom 0.381: v143.51,101.6 143.51,80.01 E12.14 | v66.04,63.5 66.04,71.12 E23.14 | D6.A 15.24,95.89 14.61,95.25 14.61,81.92 RN1.11 | v83.82,93.98 80.01,90.17 76.83,90.17 76.83,88.27 77.47,87.63 80.01,87.63 80.64,87 80.64,85.72 80.01,85.09 77.47,85.09 75.56,83.19 v75.56,76.2
PD_6  (via drill 0.61)
  Top 0.381: v26.04,85.09 20.32,85.09 19.05,83.82 RN1.13 | 146.05,100.97 144.78,100.97 144.15,100.33 108.58,100.33 107.31,99.06 XESS.81 | v181.61,100.97 146.05,100.97 | v39.37,113.03 88.9,113.03 91.44,110.49 136.53,110.49 146.05,100.97
  Bottom 0.381: 27.94,87 v26.04,85.09 | 27.94,87 D7.A | E13.3 126.36,88.27 126.36,92.71 121.28,97.79 106.68,97.79 XESS.81 | v181.61,100.97 181.61,90.17 E1.3 | 27.94,87 28.57,86.36 28.57,85.72 29.21,85.09 37.47,85.09 37.47,95.25 36.2,96.52 36.2,107.95 36.83,108.58 36.83,110.49 v39.37,113.03
PD_7  (via drill 0.61)
  Top 0.381: v127.64,93.98 131.44,97.79 137.79,97.79 | 137.79,97.79 139.06,99.06 XESS.10 | v175.26,95.25 172.72,97.79 158.12,97.79 | 158.12,97.79 137.79,97.79 | v2.54,99.69 v26.04,99.69 | v2.54,50.16 15.88,36.83 127.64,36.83 144.15,53.34 v157.48,53.34 | v158.12,96.52 158.12,97.79
  Bottom 0.381: RN1.15 22.86,93.98 D8.A 23.5,96.52 26.04,99.06 v26.04,99.69 | v127.64,93.98 127.64,87 E13.4 | v175.26,95.25 175.26,90.17 179.07,90.17 E1.4 | v2.54,50.16 v2.54,99.69 | v157.48,53.34 158.12,53.98 v158.12,96.52
PD_8  (via drill 0.61)
  Top 0.381: v135.25,94.61 137.16,96.52 v151.76,96.52 | v129.54,76.2 E13.7 | v179.71,81.92 179.07,82.55 v167,82.55 | v180.97,76.2 E1.7 | v59.69,40.64 62.23,38.1 v127,38.1
  Bottom 0.381: D9.A 53.34,91.44 RN2.15 53.98,87 53.98,53.34 59.69,47.62 v59.69,40.64 | v135.25,94.61 135.25,74.93 130.81,74.93 v129.54,76.2 129.54,40.64 v127,38.1 | 153.03,97.79 153.67,98.42 153.67,118.11 154.94,119.38 XESS.27 | 153.03,97.79 v151.76,96.52 | v180.97,76.2 180.97,80.64 v179.71,81.92 | v167,82.55 164.47,85.09 164.47,92.08 158.75,97.79 153.03,97.79
PD_9  (via drill 0.61)
  Top 0.381: v128.27,80.01 148.59,80.01 151.13,77.47 187.32,77.47 187.32,75.56 E1.8 | v58.42,107.95 59.69,109.22 v128.27,109.22
  Bottom 0.381: 57.78,105.41 58.42,104.78 58.42,86.36 RN2.13 | 57.78,105.41 56.52,105.41 48.26,97.16 D10.A | E13.8 122.56,75.56 122.56,79.38 123.19,80.01 v128.27,80.01 128.91,80.01 128.91,97.79 128.27,98.42 v128.27,109.22 128.27,140.34 130.81,142.88 130.81,144.15 132.72,146.05 152.4,146.05 XESS.28 | 57.78,105.41 58.42,106.05 v58.42,107.95
PD_10  (via drill 0.61)
  Top 0.381: v65.41,80.01 62.23,80.01 60.96,78.74 RN2.11 | v65.41,95.25 64.14,96.52 57.78,96.52 55.88,98.42 45.72,98.42 43.81,96.52 D11.A | v135.25,66.04 146.69,54.61 182.25,54.61 194.94,67.31 194.94,73.03 193.68,73.03 E1.13 | v144.15,73.66 142.88,72.39 134.62,72.39 133.35,73.66 E13.13 | v85.09,140.34 87.63,142.88 87.63,146.05 146.69,146.05 149.22,143.51 XESS.29
  Bottom 0.381: v65.41,80.01 v65.41,95.25 67.31,97.16 67.31,103.5 68.58,104.78 68.58,123.83 v85.09,140.34 | v135.25,66.04 135.25,70.48 E13.13 | v144.15,73.66 144.15,74.93 148.59,74.93 149.22,75.56 149.22,92.08 148.59,92.71 148.59,141.6 149.86,142.88 XESS.29
PD_11  (via drill 0.61)
  Top 0.381: v51.44,71.12 53.34,71.12 RN2.9 | v40.64,83.19 40.64,87 v39.37,87 | E1.14 191.13,78.11 191.13,85.09 194.31,85.09 201.29,92.08 201.29,131.44 191.13,131.44 186.69,135.89 186.69,140.97 145.41,140.97 142.88,143.51 XESS.32 | v55.88,53.98 57.15,52.7 60.33,52.7 73.66,39.37 v123.19,39.37
  Bottom 0.381: v51.44,71.12 51.44,80.64 49.53,82.55 40.64,82.55 v40.64,83.19 | v39.37,87 38.73,87.63 38.73,96.52 D12.A | 133.99,80.01 133.99,97.79 133.35,98.42 133.35,107.31 134.62,108.58 134.62,135.25 142.24,142.88 XESS.32 | 133.99,80.01 133.99,78.11 E13.14 | v123.19,39.37 127,43.18 127,76.83 130.18,80.01 133.99,80.01 | v55.88,53.98 RN2.9
RTS  (via drill 0.61)
  Top 0.381: v152.4,118.11 58.42,118.11 57.15,119.38 E24.10
  Bottom 0.381: v152.4,118.11 153.67,119.38 153.67,144.15 154.31,144.78 157.48,144.78 XESS.26
RUN  (via drill 0.61)
  Top 0.381: v88.9,125.73 173.99,125.73 E4.1
  Bottom 0.381: v88.9,125.73 78.74,115.57 XESS.70
RXD  (via drill 0.61)
  Top 0.381: v135.89,124.46 E24.12
  Bottom 0.381: v135.89,124.46 144.78,133.35 XESS.31
SKIP  (via drill 0.61)
  Top 0.381: v38.73,85.09 33.66,85.09 33.66,75.56 34.29,74.93 36.83,74.93 38.1,73.66 41.27,73.66 41.27,70.48 41.91,69.85 44.45,69.85 46.99,72.39 50.8,72.39 54.61,76.2 RN2.10 | v60.96,95.25 60.33,94.61 43.18,94.61 41.27,96.52 D13.A
  Bottom 0.381: v38.73,85.09 39.37,85.09 40.64,86.36 D13.A | v60.96,95.25 60.96,98.42 67.31,104.78 67.31,144.78 87,144.78 87.63,144.15 87.63,142.24 94.61,142.24 95.25,142.88 95.25,144.78 127.64,144.78 128.91,143.51 XESS.37
T2  (via drill 0.61)
  Top 0.381: v26.67,24.13 26.67,20.95 25.4,20.95 SV3.NN
  Bottom 0.381: R52.1 SV3.NN | v26.67,24.13 SV1.30
TS1  (via drill 0.61)
  Top 0.381: v167,135.89 173.99,135.89 E5.1
  Bottom 0.381: v167,135.89 160.02,128.91 XESS.18
TS3
  Bottom 0.381: E5.6 180.34,146.05 177.8,148.59 177.8,150.5 177.16,151.13 168.91,151.13 168.91,107.31 162.56,100.97 XESS.19
TXD  (via drill 0.61)
  Top 0.381: v98.42,123.19 58.42,123.19 57.15,121.92 E24.11
  Bottom 0.381: v98.42,123.19 118.75,143.51 XESS.41
V2
  Bottom 0.381: R54.1 SV3.TT 20.32,21.59 23.5,21.59 24.13,22.23 SV1.32
VCC
  Top 0.381: R54.2 R53.2 R52.2 R51.2 R50.2 R49.2 R48.2 R47.2 R46.2 R45.2 R44.2 R43.2 R42.2 R41.2 R40.2 R39.2 R38.2 R37.2 R36.2 R35.2 R34.2 R33.2 R32.2 R31.2 R30.2 R29.2 R28.2 R27.2 R26.2 R25.2 R24.2 R23.2 R22.2 R21.2 R20.2 R19.2 R18.2 R17.2 R16.2 R15.2 R14.2 R13.2 R12.2 R11.2 R10.2 R9.2 R8.2 R7.2 R6.2 R5.2 R4.2 R3.2 R2.2 R1.2 | C14.1 115.57,56.52 121.92,56.52 130.81,65.41 C13.1 131.44,66.04 132.72,67.31 144.15,67.31 145.41,66.04 C12.1 | 129.54,92.71 130.81,91.44 E13.20 | 129.54,92.71 119.38,92.71 118.11,91.44 E16.8 115.57,91.44 114.3,92.71 104.14,92.71 102.87,91.44 E19.8 100.97,90.81 100.97,89.53 E19.7 E19.2 92.71,88.9 90.17,91.44 E22.8 85.09,91.44 83.82,92.71 73.66,92.71 | 129.54,92.71 144.78,92.71 146.05,91.44 E12.20 148.59,91.44 149.86,92.71 165.1,92.71 | E5.8 177.16,142.88 185.42,142.88 C5.1 | C2.1 184.78,105.41 184.15,104.78 177.16,104.78 E2.8 | 174.62,57.15 163.19,57.15 161.93,55.88 C9.1 | 174.62,57.15 175.9,55.88 C6.1 | 185.42,64.77 180.97,64.77 179.71,66.04 E6.8 | 185.42,64.77 189.87,64.77 191.13,66.04 C1.1 | 174.62,57.15 174.62,59.69 180.34,59.69 185.42,64.77 | 175.26,92.71 176.53,91.44 E8.8 | 165.1,92.71 175.26,92.71 | 165.1,92.71 163.83,91.44 E11.8 | 175.26,92.71 190.5,92.71 191.77,91.44 E1.20 | C8.1 175.9,81.28 174.62,80.01 166.37,80.01 165.1,78.74 E10.8 | C7.1 175.9,68.58 174.62,67.31 165.1,67.31 163.83,66.04 E9.8 | 27.94,135.89 20.32,135.89 19.05,134.62 E29.14 | 27.94,135.89 29.21,134.62 E28.16 | 40.64,135.89 41.91,134.62 E26.14 | 40.64,135.89 27.94,135.89 | 40.64,135.89 53.34,135.89 54.61,134.62 E24.16 | C27.1 29.84,66.04 31.11,67.31 40.01,67.31 41.27,66.04 C25.1 62.87,66.04 64.14,67.31 71.75,67.31
  Top 0.381: 71.75,67.31 70.48,66.04 C23.1 | 71.75,67.31 83.19,67.31 84.45,68.58 C21.1 | C29.1 17.14,116.84 18.41,115.57 27.3,115.57 28.57,114.3 C28.1 29.84,114.3 31.11,115.57 43.81,115.57 | 43.81,115.57 52.7,115.57 53.98,114.3 C24.1 | 43.81,115.57 42.55,116.84 C26.1 | E17.2 E17.7 100.97,64.14 100.97,65.41 E17.8 | C20.1 85.72,55.88 87,54.61 98.42,54.61 99.69,55.88 C17.1 | E18.7 E18.2 | E21.8 87.63,78.74 88.9,80.01 98.42,80.01 99.69,81.28 C19.1 | E27.20 31.75,91.44 33.02,92.71 40.64,92.71 41.91,91.44 E25.20 44.45,91.44 45.72,92.71 73.66,92.71 | 73.66,92.71 72.39,91.44 E23.20 | E20.8 87.63,66.04 88.9,67.31 98.42,67.31 99.69,68.58 C18.1
  Bottom 0.381: C38.+ 10.79,29.21 15.24,24.77 15.24,8.26 20.32,3.17 R54.2 | R1.2 180.34,3.17 184.15,6.99 184.15,23.5 190.5,29.84 C39.+ 192.41,31.75 194.31,33.66 194.31,60.96 191.77,63.5 C1.1 | 114.94,66.04 114.94,68.58 C15.1 115.57,69.22 114.94,69.85 114.94,81.28 | 114.94,66.04 114.94,57.15 115.57,56.52 C14.1 | 114.94,66.04 E14.8 | E15.8 115.57,80.01 C16.1 114.94,81.28 | 114.94,81.28 114.94,89.53 E16.8 | 173.99,116.84 175.26,118.11 E3.8 | 173.99,116.84 173.99,109.22 175.26,107.95 E2.8 175.26,105.41 176.53,104.14 176.53,91.44 E8.8 | 173.99,129.54 175.26,130.81 E4.8 | 173.99,116.84 173.99,129.54 | 186.69,116.2 185.42,117.47 C3.1 | 186.69,116.2 186.69,107.31 185.42,106.05 C2.1 | 186.69,116.2 186.69,128.91 185.42,130.18 C4.1 | 173.99,129.54 173.99,142.24 175.26,143.51 E5.8 | E6.8 176.53,67.31 C7.1 | E7.8 176.53,80.01 C8.1 | E9.8 161.93,66.67 161.93,67.31 161.29,67.94 C10.1 161.29,69.22 160.66,69.85 160.66,81.28 | E10.8 161.93,79.38 161.93,80.01 161.29,80.64 C11.1 160.66,81.28 | 160.66,81.28 160.66,89.53 E11.8 | E26.4 34.92,127.64 34.92,128.91 E26.3 36.83,129.54 38.1,130.81 40.64,130.81 40.64,132.08 E26.14 | E20.8 85.09,67.31 C21.1 | C41.2 38.1,109.86 41.91,113.67 C26.1 | E17.8 100.97,66.67 100.97,67.31 100.33,67.94 C18.1 103.5,68.58 103.5,80.64 | E17.7 99.69,61.59 99.69,55.88 C17.1 | E21.8 85.09,80.01 C22.1 | E18.8 100.97,78.11 100.97,76.83 E18.7 | C19.1 100.33,80.64 100.97,80.01 100.97,79.38 E18.8 | 103.5,80.64 103.5,87 E19.7 | 103.5,80.64 E18.8 | C28.1 29.21,113.67 30.48,112.39 E27.20 | E24.16 53.98,132.72 53.98,114.3 C24.1 | 12.7,146.69 FUSE.2 | E29.14 17.14,135.25
  Bottom 1.905: 12.7,146.69 17.14,142.24 17.14,135.25

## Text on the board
Top: Posibus DMux | VCC
Bottom: Posibus DMux | GND
tPlace: Posibus DMux
tValues: AC | * | * | * | * | * | * | * | * | * | Side 1 | BMB | BAC | * | * | * | * | * | * | * | * | * | Side 2 | * | * | * | * | * | * | * | * | * | * | * | * | * | * | * | * | * | *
